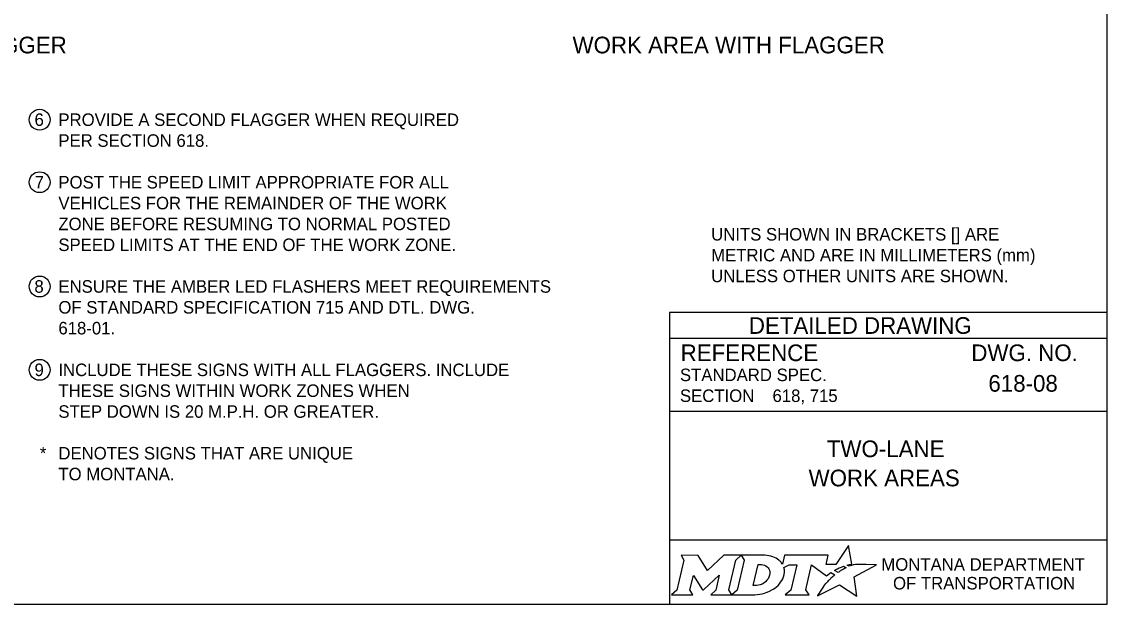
# Model space of a CAD drawing. Extents: x 49991.4 to 50021, y 49987.6 to 50011.4.
# Drawn here: x 50003.41 to 50008.61, y 50000.06 to 50002.86 of the extents above; entities that cross this region are included whole.
import ezdxf

# ---------------------------------------------------------------- set-up
doc = ezdxf.new("R2010")
doc.units = 0
doc.layers.add('Level 1', color=7, linetype='Continuous')
doc.layers.add('Level 2', color=7, linetype='Continuous')

msp = doc.modelspace()

# ---------------------------------------------------------------- linework, layer by layer
at = {"layer": 'Level 1'}
msp.add_lwpolyline([(50008.6146, 50011.2628), (50000.3356, 50011.2628), (50000.3356, 50000.0624), (50008.6146, 50000.0624)], close=True, dxfattribs=at)
at = {"layer": 'Level 2'}
for p, q in [((50008.6146, 50001.4624), (50006.5146, 50001.4624)), ((50006.5146, 50001.4624), (50006.5146, 50000.0624)), ((50008.6146, 50001.3374), (50006.5146, 50001.3374)), ((50008.2507, 50001.1223), (50008.2507, 50001.1223)), ((50007.0089, 50001.0629), (50007.0089, 50001.0629)), ((50008.6146, 50000.9874), (50006.5146, 50000.9874)), ((50007.5646, 50000.7383), (50007.5646, 50000.7383)), ((50008.6146, 50000.3693), (50006.5146, 50000.3693))]:
    msp.add_line(p, q, dxfattribs=at)
for points in [[(50006.5701, 50000.2974), (50006.5842, 50000.274), (50006.5507, 50000.1307), (50006.525, 50000.1082), (50006.6266, 50000.1082), (50006.6131, 50000.131), (50006.6293, 50000.2011), (50006.673, 50000.1321), (50006.6783, 50000.1321), (50006.7534, 50000.2016), (50006.737, 50000.1305), (50006.7123, 50000.1085), (50006.8139, 50000.1085), (50006.8001, 50000.1318), (50006.8333, 50000.2742)], [(50006.8333, 50000.2742), (50006.8586, 50000.2974), (50006.7762, 50000.2974), (50006.6966, 50000.2244), (50006.6521, 50000.2971), (50006.5701, 50000.2974)], [(50006.9722, 50000.2974), (50006.8586, 50000.2974), (50006.8733, 50000.2745), (50006.8394, 50000.1307), (50006.8139, 50000.1085), (50006.9245, 50000.1085)], [(50007.3771, 50000.2447), (50007.3668, 50000.2503), (50007.3784, 50000.2531), (50007.39, 50000.2551), (50007.3726, 50000.3452), (50007.3131, 50000.2539), (50007.2658, 50000.2532), (50007.2761, 50000.2973), (50007.0669, 50000.2974), (50007.0568, 50000.2549), (50007.051, 50000.2632)], [(50006.9962, 50000.2107), (50006.995, 50000.2026), (50006.9918, 50000.1933), (50006.9876, 50000.1851), (50006.982, 50000.1776), (50006.9755, 50000.1707), (50006.9676, 50000.1644), (50006.9593, 50000.1597), (50006.9502, 50000.1558), (50006.9411, 50000.1535), (50006.9319, 50000.1526), (50006.916, 50000.1526), (50006.9396, 50000.2526), (50006.9556, 50000.2526), (50006.9632, 50000.252), (50006.9708, 50000.2501), (50006.9774, 50000.2471), (50006.9835, 50000.2429), (50006.9883, 50000.2379), (50006.992, 50000.2319), (50006.9947, 50000.2257), (50006.9963, 50000.2183), (50006.9963, 50000.2153), (50006.9962, 50000.2107)], [(50007.0636, 50000.2383), (50007.0882, 50000.2514), (50007.1251, 50000.2514), (50007.0965, 50000.1309), (50007.069, 50000.1082), (50007.1852, 50000.1082), (50007.1682, 50000.1311), (50007.1964, 50000.2513), (50007.2677, 50000.1996), (50007.2888, 50000.2147), (50007.3085, 50000.2038)], [(50007.2527, 50000.1479), (50007.2374, 50000.1235), (50007.2327, 50000.116), (50007.2269, 50000.1074), (50007.2246, 50000.1031), (50007.3299, 50000.1562), (50007.4138, 50000.1011), (50007.4007, 50000.1938), (50007.5076, 50000.2522), (50007.4583, 50000.253), (50007.4282, 50000.2534), (50007.4074, 50000.2537), (50007.4006, 50000.2522), (50007.3957, 50000.251), (50007.3873, 50000.2487), (50007.3771, 50000.2447)], [(50007.3267, 50000.2171), (50007.3243, 50000.2154), (50007.306, 50000.225), (50007.3163, 50000.2307), (50007.3204, 50000.2329), (50007.329, 50000.2369), (50007.3347, 50000.2395), (50007.3426, 50000.2425), (50007.3499, 50000.2452), (50007.3617, 50000.2378), (50007.3577, 50000.2357), (50007.3531, 50000.2332), (50007.3489, 50000.231), (50007.3439, 50000.2281), (50007.342, 50000.227), (50007.3393, 50000.2254), (50007.3368, 50000.224), (50007.3345, 50000.2224), (50007.3319, 50000.2206), (50007.3292, 50000.2188), (50007.3267, 50000.2171)], [(50007.2666, 50000.164), (50007.2666, 50000.164)], [(50006.9702, 50000.1158), (50006.9786, 50000.1184), (50006.9916, 50000.1238), (50007.012, 50000.1348)]]:
    msp.add_lwpolyline(points, dxfattribs=at)
for centre in [(50003.4938, 50002.3872), (50003.4938, 50002.0872), (50003.4938, 50001.5872), (50003.4938, 50001.1872)]:
    msp.add_circle(centre, 0.05, dxfattribs=at)
for centre, radius, start, end in [((50006.9513, 50000.2363), 0.1183, 300.9103, 339.1383), ((50006.9953, 50000.219), 0.0709, 339.5329, 15.8582)]:
    msp.add_arc(centre, radius, start, end, dxfattribs=at)
for centre, major_axis, ratio, start_param, end_param in [((50006.9701, 50000.25), (0.0834, -0.0037), 0.568097, 0.61298, 1.570796), ((50007.0257, 50000.2573), (0.0361, -0.0295), 0.469099, 1.225588, 1.570796), ((50007.2974, 50000.1941), (-0.0112, -0.0097), 0.021651, 3.157348, 6.283185), ((50007.2597, 50000.1559), (-0.00694, -0.00806), 0.008222, 0, 3.137361), ((50007.2764, 50000.1742), (-0.0098, -0.0102), 0.016458, 3.141593, 6.279097), ((50006.9248, 50000.2568), (0, 0.1484), 0.987302, 3.139398, 3.456847)]:
    msp.add_ellipse(centre, major_axis=major_axis, ratio=ratio, start_param=start_param, end_param=end_param, dxfattribs=at)

# ---------------------------------------------------------------- texts
for s, height, p in [('WORK AREA WITH NO FLAGGER', 0.08, (50001.936, 50002.7055)), ('WORK AREA WITH FLAGGER', 0.08, (50006.0498, 50002.7055)), ('6', 0.06, (50003.4694, 50002.3574)), ('PROVIDE A SECOND FLAGGER WHEN REQUIRED ', 0.06, (50003.5838, 50002.3572)), ('PER SECTION 618.', 0.06, (50003.5838, 50002.2572)), ('7', 0.06, (50003.47, 50002.0572)), ('POST THE SPEED LIMIT APPROPRIATE FOR ALL ', 0.06, (50003.5838, 50002.0572)), ('VEHICLES FOR THE REMAINDER OF THE WORK', 0.06, (50003.5838, 50001.9572)), ('ZONE BEFORE RESUMING TO NORMAL POSTED ', 0.06, (50003.5838, 50001.8572)), ('UNITS SHOWN IN BRACKETS [] ARE ', 0.06, (50006.7146, 50001.8076)), ('SPEED LIMITS AT THE END OF THE WORK ZONE.', 0.06, (50003.5838, 50001.7572)), ('METRIC AND ARE IN MILLIMETERS (mm) ', 0.06, (50006.7146, 50001.7076)), ('UNLESS OTHER UNITS ARE SHOWN.', 0.06, (50006.7146, 50001.6076)), ('8', 0.06, (50003.4688, 50001.5572)), ('ENSURE THE AMBER LED FLASHERS MEET REQUIREMENTS', 0.06, (50003.5838, 50001.5572)), ('OF STANDARD SPECIFICATION 715 AND DTL. DWG. ', 0.06, (50003.5838, 50001.4572)), ('618-01.', 0.06, (50003.5838, 50001.3572)), ('DETAILED DRAWING', 0.0799, (50006.8956, 50001.3599)), ('REFERENCE', 0.08, (50006.5682, 50001.229)), ('DWG. NO.', 0.08, (50007.9624, 50001.229)), ('9', 0.06, (50003.4692, 50001.1572)), ('INCLUDE THESE SIGNS WITH ALL FLAGGERS. INCLUDE ', 0.06, (50003.5838, 50001.1572)), ('STANDARD SPEC.', 0.06, (50006.5649, 50001.133)), ('618-08', 0.08, (50008.0443, 50001.0823)), ('THESE SIGNS WITHIN WORK ZONES WHEN', 0.06, (50003.5838, 50001.0572)), ('SECTION', 0.06, (50006.5649, 50001.033)), ('618, 715', 0.06, (50007.0089, 50001.0329)), ('STEP DOWN IS 20 M.P.H. OR GREATER.', 0.06, (50003.5838, 50000.9572)), ('DENOTES SIGNS THAT ARE UNIQUE ', 0.06, (50003.5838, 50000.7572)), ('TWO-LANE', 0.08, (50007.2692, 50000.7683)), ('*', 0.06, (50003.4946, 50000.7572)), ('TO MONTANA.', 0.06, (50003.5838, 50000.6572)), ('WORK AREAS', 0.08, (50007.1819, 50000.6283)), ('MONTANA DEPARTMENT', 0.06, (50007.5308, 50000.2236)), ('OF TRANSPORTATION', 0.06, (50007.587, 50000.1336))]:
    msp.add_text(s, height=height, dxfattribs=at).set_placement(p)

doc.saveas('drawing.dxf')
